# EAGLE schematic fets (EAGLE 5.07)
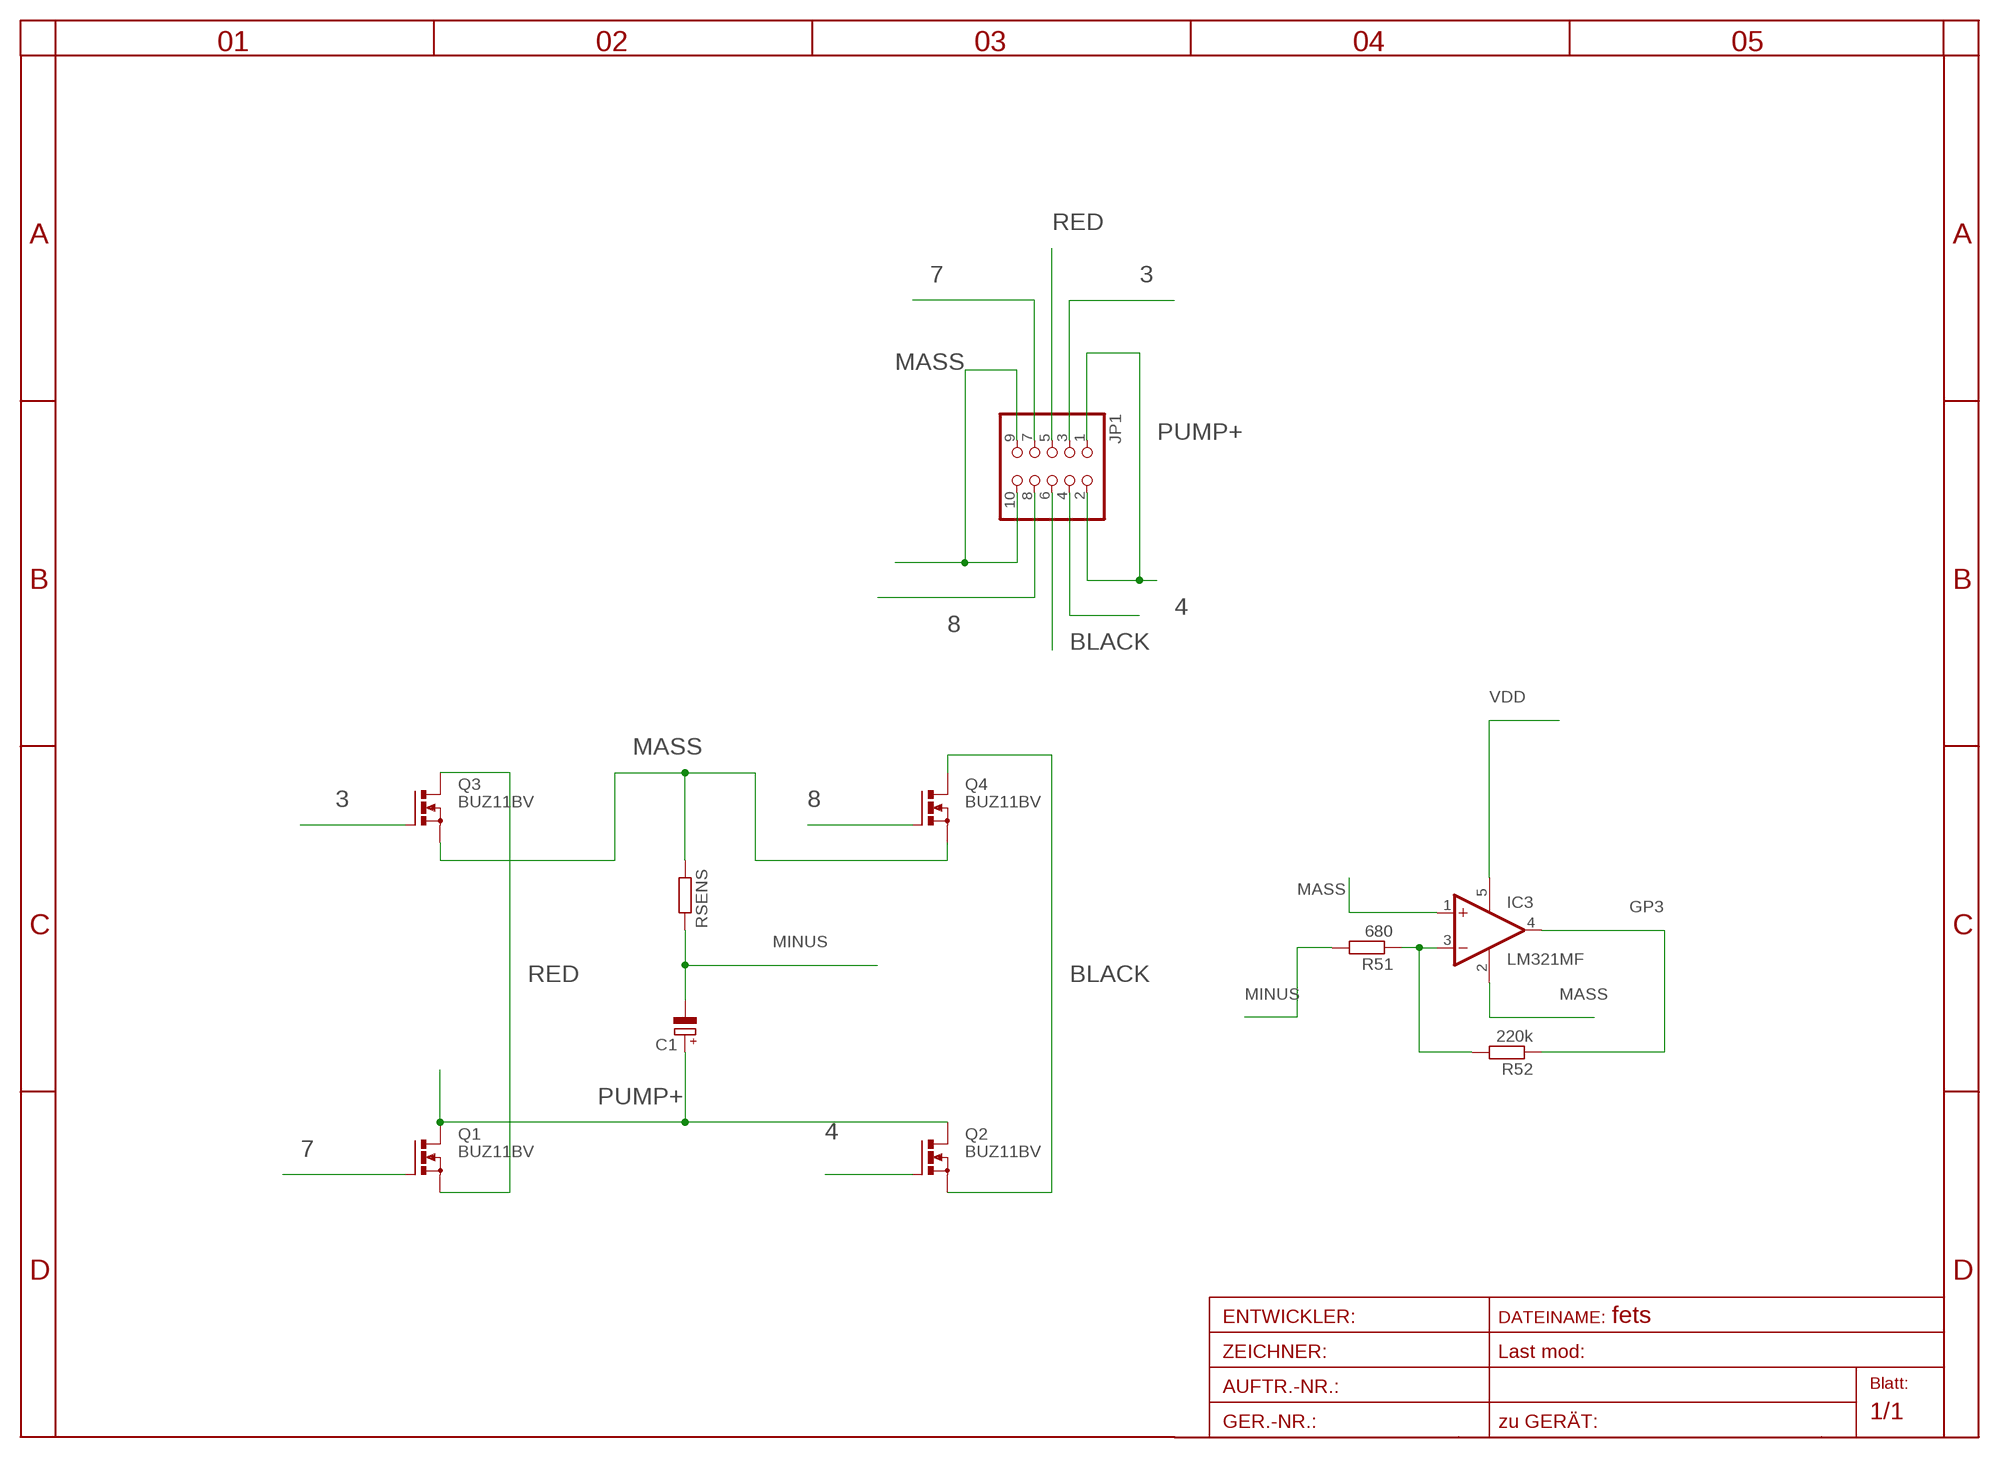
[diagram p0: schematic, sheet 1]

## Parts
C1  CPOL-EUE5-13  [E5-13]
IC3  LM321MF  [SOT23-5]
JP1  PINHD-2X5  [2X05]
Q1  BUZ11BV  [TO220BV]
Q2  BUZ11BV  [TO220BV]
Q3  BUZ11BV  [TO220BV]
Q4  BUZ11BV  [TO220BV]
R51  680  R-EU_0207/10  [0207/10]
R52  220k  R-EU_0207/10  [0207/10]
RSENS  R-EU_0207/10  [0207/10]

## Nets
3: JP1.3 Q3.G
4: JP1.4 Q2.G
7: JP1.7 Q1.G
8: JP1.8 Q4.G
BLACK: JP1.6 Q2.S Q4.D
GP3: IC3.4(OUT) R52.1
MASS: IC3.1(+IN) IC3.2(V-) JP1.9 JP1.10 Q3.S Q4.S RSENS.1
MINUS: C1.- R51.2 RSENS.2
N$52: IC3.3(-IN) R51.1 R52.2
PUMP+: C1.+ JP1.1 JP1.2 Q1.D Q2.D
RED: JP1.5 Q1.S Q3.D
VDD: IC3.5(V+)

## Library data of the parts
C1 = rcl:CPOL-EU: POLARIZED CAPACITOR, European symbol
IC3 = linear:LM321?*: Low Power Single Op Amp Source: http://cache.national.com/ds/LM/LM321.pdf
JP1 = pinhead:PINHD-2X5: PIN HEADER
Q1-Q4 = transistor-power:BUZ11: N-CHANNEL MOS FET
R51 R52 RSENS = rcl:R-EU_: RESISTOR, European symbol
